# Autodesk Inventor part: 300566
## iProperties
Created: 2007-11
Part Number: 300566
Document SubType Name: Modeling
Designer: TH
Density: 2.71 g/cm^3
Mass: 9.33314 g
Surface Area: 70.624 cm^2
Volume: 3.44396 cm^3
Material: Aluminum-6061
Description: WIRE CONNECTOR BAR
Component Category: Back Component
Author: TH
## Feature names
1. Extrusion1
2. Extrusion2
